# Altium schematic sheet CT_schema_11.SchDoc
size 226 x 144 mm
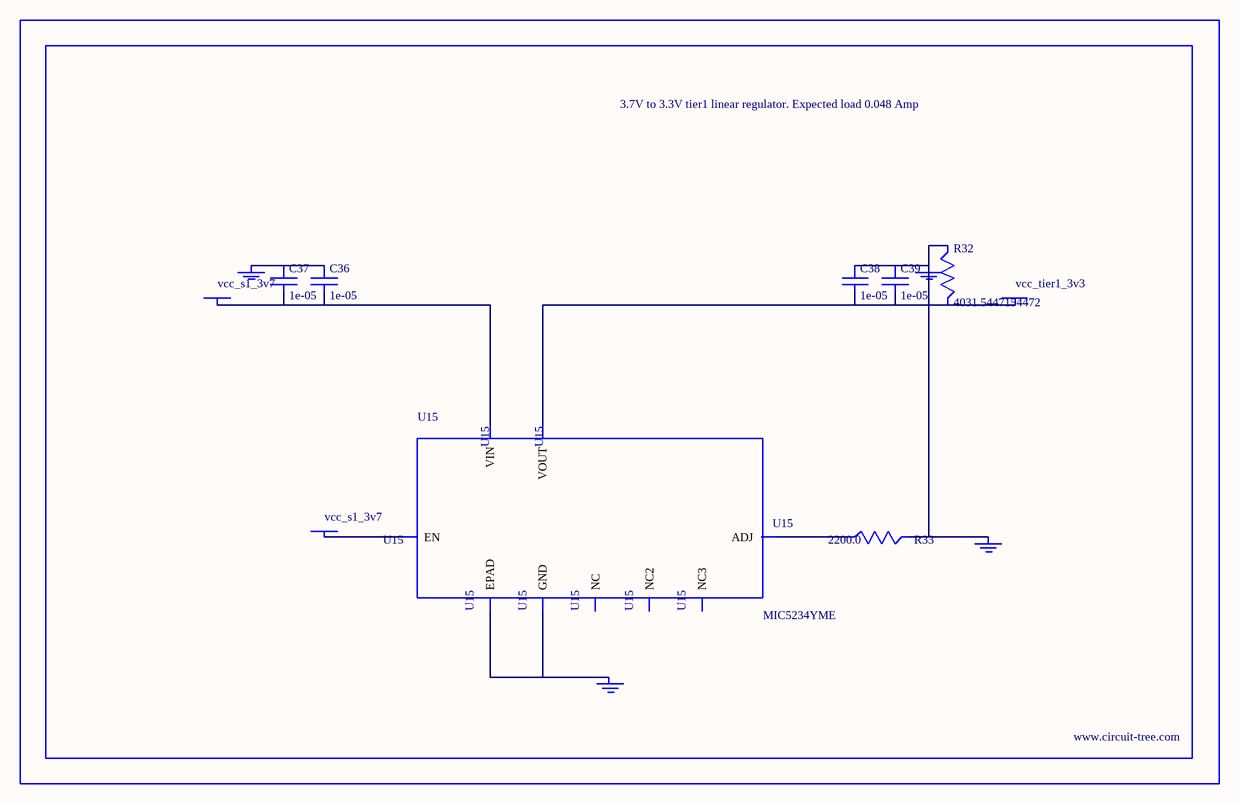
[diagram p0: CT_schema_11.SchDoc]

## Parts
BORDER10  (no value)
C36  1e-05  [C1210]
C37  1e-05  [C1210]
C38  1e-05  [C1210]
C39  1e-05  [C1210]
GND_INSTANCE_10_0  (no value)
GND_INSTANCE_10_1  (no value)
GND_INSTANCE_10_2  (no value)
GND_INSTANCE_10_3  (no value)
POWER_INSTANCE_10_0  vcc_tier1_3v3
POWER_INSTANCE_10_1  vcc_s1_3v7
POWER_INSTANCE_10_2  vcc_s1_3v7
R32  4031.5447154472  [R0603]
R33  2200.0  [R0603]
U15  MIC5234YME  [SOIC-8_EP]

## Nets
NetC36_1: C36.1 C37.1 GND_INSTANCE_10_3.0(GND)
NetC36_2: C36.2 C37.2 POWER_INSTANCE_10_2.0(PWR) U15.8(VIN)
NetC38_1: C38.1 C39.1 GND_INSTANCE_10_0.0(GND) GND_INSTANCE_10_1.0(GND) R32.1 R33.2
NetC38_2: C38.2 C39.2 POWER_INSTANCE_10_0.0(PWR) R32.2 U15.1(VOUT)
NetGND_INSTANCE_10_2_0: GND_INSTANCE_10_2.0(GND) U15.7(GND) U15.EPAD
NetPOWER_INSTANCE_10_1_0: POWER_INSTANCE_10_1.0(PWR) U15.5(EN)
NetR33_1: R33.1 U15.4(ADJ)

Not connected (* = marked no-connect by the designer): U15 2(NC) 3(NC2) 6(NC3)

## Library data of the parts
BORDER10 = BORDER_PAGE10
C36-C39 = C1210C106K5PACTU
GND_INSTANCE_10_0-GND_INSTANCE_10_3 = GND
POWER_INSTANCE_10_0-POWER_INSTANCE_10_2 = PWR
R32 = R32
R33 = RC0603JR-072K2L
